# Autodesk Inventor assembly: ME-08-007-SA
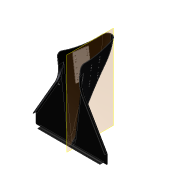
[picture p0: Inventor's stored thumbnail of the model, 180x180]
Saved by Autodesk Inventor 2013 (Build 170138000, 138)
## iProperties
Shininess: 20.0
Length Units: 11269
Angle Units: 11279
Time Units: 11290
Mass Units: 11283
Length Display Precision: 3
Angle Display Precision: 2
Created: 2001-04
Part Number: ME-08-007-SA
Document SubType Name: Baugruppe
Designer: dl
Density: 0.0
Volumn: 0.0
Area: 0.0
PropertySet Name: Model Information
Control State: 0
Master: False
Checked Out: False
Author: dl
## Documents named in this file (4)
- C:\Webworld\Webworld2014\ATC2013\Assemblies\ATC-Baby Carriage\FOOTBOARD\ME-08-007-SA.iam
- C:\Webworld\Webworld2014\ATC2013\Assemblies\ATC-Baby Carriage\FOOTBOARD\Footboard.ipt
- C:\Webworld\Webworld2014\ATC2013\Assemblies\ATC-Baby Carriage\FOOTBOARD\Reinforcing_plate.ipt
- C:\Webworld\Webworld2014\ATC2013\Assemblies\ATC-Baby Carriage\FOOTBOARD\Rivet 5mm.ipt
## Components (11 placed, 3 different names)
1. Footboard:1 — Mate:1, Insert:1, Insert:2, Insert:3, Insert:4, Insert:5, Insert:6, Insert:7, Insert:8, Insert:9, Insert:10, Insert:11, Insert:12
2. Reinforcing_plate:1 — Mate:1, Insert:1, Insert:2
3. Reinforcing_plate:2 — Insert:3, Insert:4
4. Rivet 5mm:1 — Insert:6
5. Rivet 5mm:2 — Insert:7
6. Rivet 5mm:3 — Insert:8
7. Rivet 5mm:4 — Insert:5
8. Rivet 5mm:5 — Insert:9
9. Rivet 5mm:6 — Insert:11
10. Rivet 5mm:7 — Insert:12
11. Rivet 5mm:8 — Insert:10
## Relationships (13: Insert 12, Mate 1)
- Mate:1: Footboard:1 ↔ Reinforcing_plate:1
- Insert:1: Footboard:1 ↔ Reinforcing_plate:1
- Insert:2: Footboard:1 ↔ Reinforcing_plate:1
- Insert:3: Footboard:1 ↔ Reinforcing_plate:2
- Insert:4: Footboard:1 ↔ Reinforcing_plate:2
- Insert:5: Footboard:1 ↔ Rivet 5mm:4
- Insert:6: Footboard:1 ↔ Rivet 5mm:1
- Insert:7: Footboard:1 ↔ Rivet 5mm:2
- Insert:8: Footboard:1 ↔ Rivet 5mm:3
- Insert:9: Footboard:1 ↔ Rivet 5mm:5
- Insert:10: Footboard:1 ↔ Rivet 5mm:8
- Insert:11: Footboard:1 ↔ Rivet 5mm:6
- Insert:12: Footboard:1 ↔ Rivet 5mm:7
